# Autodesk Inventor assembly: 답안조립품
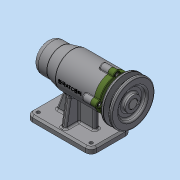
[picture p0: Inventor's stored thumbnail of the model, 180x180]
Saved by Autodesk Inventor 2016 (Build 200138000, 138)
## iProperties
Created: 2019-07
Part Number: 답안조립품
Material: 일반
Document SubType Name: Assembly
Designer: Administrator
Mass: 1312.17 g
Surface Area: 1279.89 cm^2
Volume: 392.759 cm^3
Density: 3.34091 g/cm^3
Author: Administrator
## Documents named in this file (12)
- C:\Users\Administrator\Desktop\490704V1007\답안조립품.iam
- C:\Users\Administrator\Desktop\490704V1007\본체.ipt
- C:\Users\Administrator\Desktop\490704V1007\베어링 51202.ipt
- C:\Users\Administrator\Desktop\490704V1007\어댑터슬리브.ipt
- C:\Users\Administrator\Desktop\490704V1007\축.ipt
- C:\Users\Administrator\Desktop\490704V1007\베어링 6004.ipt
- C:\Users\Administrator\Desktop\490704V1007\커버.ipt
- C:\Users\Administrator\Desktop\490704V1007\볼트 M4.ipt
- C:\Users\Administrator\Desktop\490704V1007\키 5 x 5 x 16.ipt
- C:\Users\Administrator\Desktop\490704V1007\오일 실.ipt
- C:\Users\Administrator\Desktop\490704V1007\V벨트풀리.ipt
- C:\Users\Administrator\Desktop\490704V1007\멈춤나사 M3.ipt
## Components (1 placed, 1 different names)
1. V벨트풀리:1
